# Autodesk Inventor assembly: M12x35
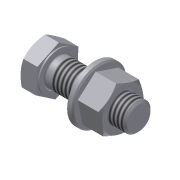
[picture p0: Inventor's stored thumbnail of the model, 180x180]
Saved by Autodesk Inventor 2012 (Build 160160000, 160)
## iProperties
Company: CAD-Verlag
Created: 2004-12
Part Number: M12x35
Document SubType Name: Assembly
Designer: jukr
Manufacturer: Standard
Standards Organization: Custom
Author: Jürgen Kronas
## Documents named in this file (4)
- C:\Daten Vault 2012 Inventor\Kapitel 6\6.4\Rollenbahn\Bibliotheken\M12x35.iam
- C:\Daten Vault 2012 Inventor\Kapitel 6\6.4\Rollenbahn\Bibliotheken\I4032000YBW6B_MIR.ipt
- C:\Daten Vault 2012 Inventor\Kapitel 6\6.4\Rollenbahn\Bibliotheken\I4017A000Q9FLB_MIR.ipt
- C:\Daten Vault 2012 Inventor\Kapitel 6\6.4\Rollenbahn\Bibliotheken\D125_2000RI1XB_MIR.ipt
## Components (3 placed, 3 different names)
1. I4032000YBW6B_MIR:1
2. I4017A000Q9FLB_MIR:1
3. D125_2000RI1XB_MIR:1
